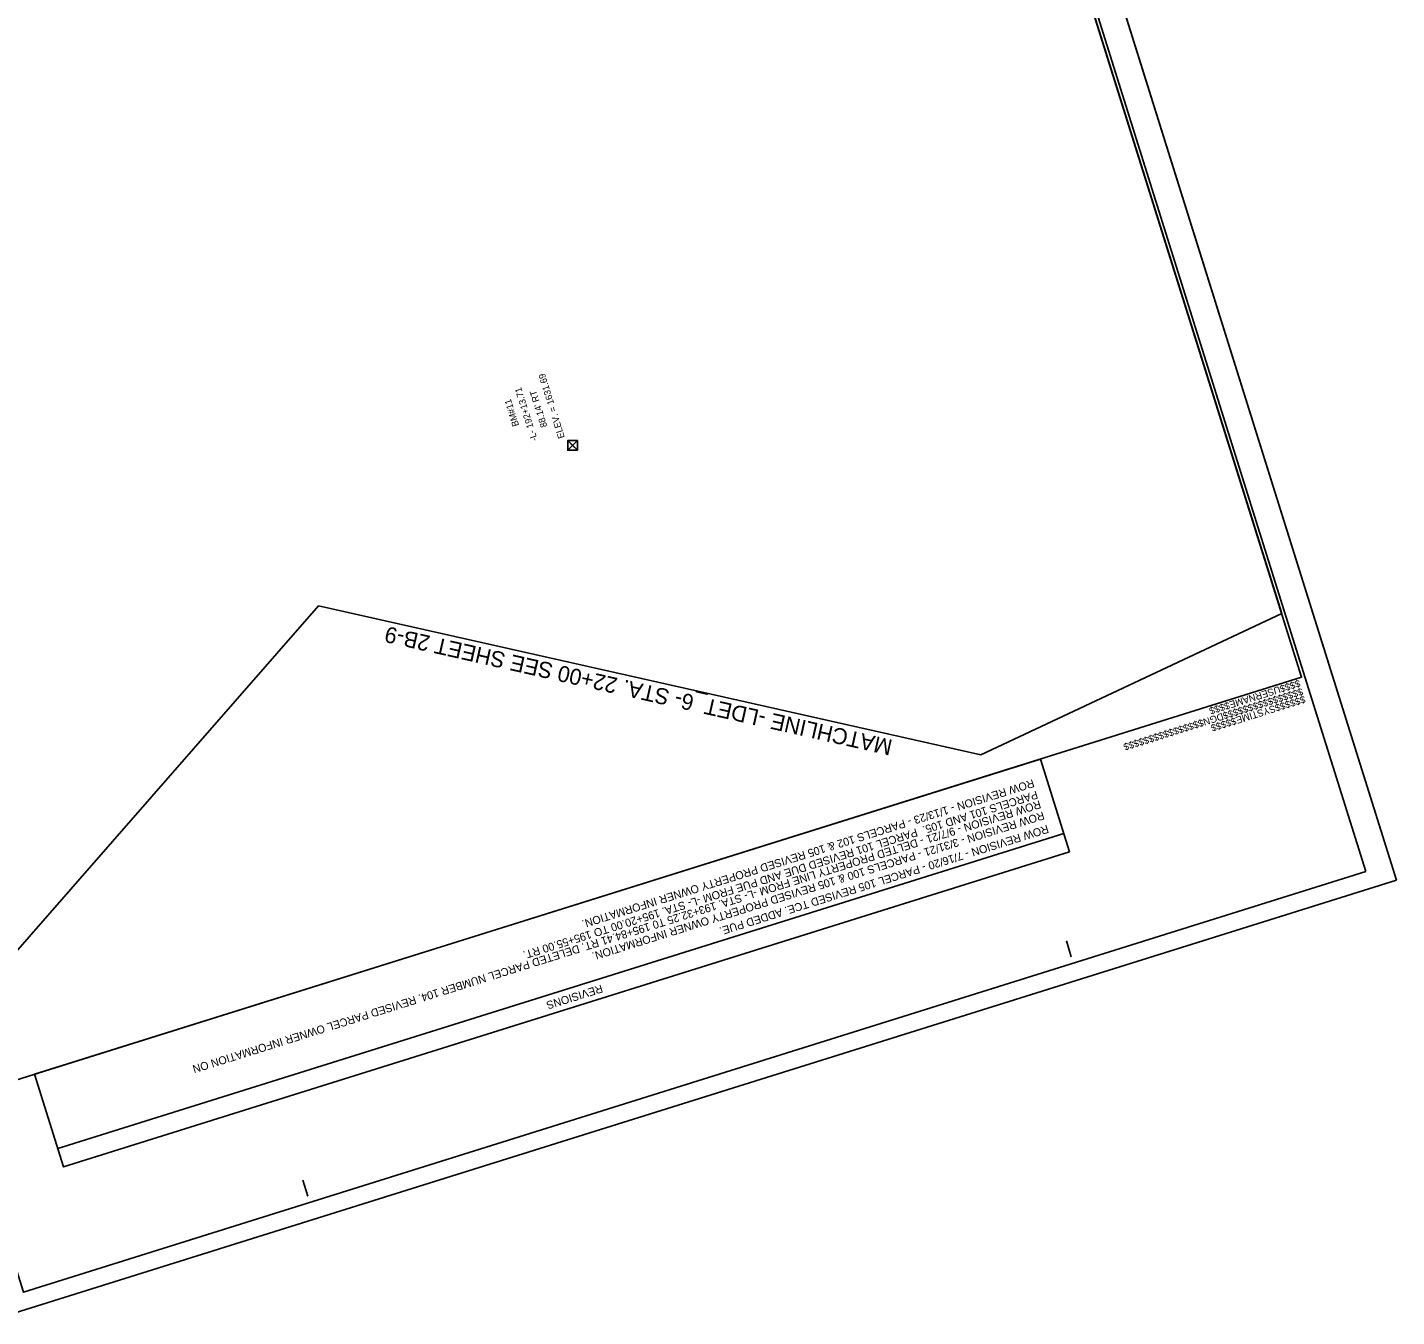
# Model space of a CAD drawing. Extents: x 473667 to 478950, y 494687 to 505998.
# Drawn here: x 474189 to 475215, y 504064 to 505031 of the extents above; entities that cross this region are included whole.
import ezdxf

# ---------------------------------------------------------------- set-up
doc = ezdxf.new("R2010")
doc.units = 0
for name, color, linetype in [('Default', 7, 'Continuous'), ('Matchline', 7, 'Continuous'), ('Matchline Text', 7, 'Continuous'), ('Sheet Block Revision CELL', 7, 'Continuous'), ('Sheet Cutting Line CELL', 7, 'Continuous'), ('Sheet Layout Plan Border', 7, 'Continuous'), ('Sheet Plan CELL', 7, 'Continuous'), ('Sheet Plan Layout CELL', 7, 'Continuous'), ('Sheet Plot Border Inside CELL', 7, 'Continuous'), ('Sheet Plot Border Outside CELL', 7, 'Continuous')]:
    doc.layers.add(name, color=color, linetype=linetype)

msp = doc.modelspace()

# ---------------------------------------------------------------- linework, layer by layer
at = {"layer": 'Default'}
msp.add_line((474597.4, 504717.3), (474597.4, 504717.3), dxfattribs=at)
msp.add_lwpolyline([(474593.8, 504720.9), (474601, 504720.9), (474601, 504713.7), (474593.8, 504713.7)], close=True, dxfattribs=at)
for points in [[(474601, 504720.9), (474593.8, 504713.7), (474597.4, 504717.3), (474601, 504713.7), (474593.8, 504720.9)], [(474597.4, 504717.3), (474601, 504720.9), (474593.8, 504720.9), (474597.4, 504717.3)], [(474597.4, 504717.3), (474593.8, 504713.7), (474601, 504713.7), (474597.4, 504717.3)]]:
    msp.add_lwpolyline(points, dxfattribs=at)
at = {"layer": 'Matchline'}
msp.add_line((474903.6, 504485.2), (474406.8, 504597), dxfattribs=at)
at = {"layer": 'Sheet Block Revision CELL'}
msp.add_line((474965.7, 504426.3), (474211.3, 504189.9), dxfattribs=at)
msp.add_lwpolyline([(474970.1, 504412.4), (474215.6, 504176.1), (474193.8, 504245.6), (474948.3, 504482)], close=True, dxfattribs=at)
at = {"layer": 'Sheet Cutting Line CELL'}
for p, q in [((475215.4, 504391.2), (474712.1, 505997.7)), ((474170.5, 504063.9), (475215.4, 504391.2))]:
    msp.add_line(p, q, dxfattribs=at)
at = {"layer": 'Sheet Layout Plan Border'}
msp.add_lwpolyline([(474406.8, 504597), (474903.6, 504485.2), (475129.2, 504591.1), (474710.6, 505927.1), (474746.7, 505812), (474670.3, 505788.1), (474619.3, 505950.9), (473859.3, 505712.8), (473919.1, 505521.9), (473753.5, 505470), (474127.2, 504277.2)], close=True, dxfattribs=at)
at = {"layer": 'Sheet Plan CELL'}
for p, q in [((475144.1, 504543.4), (475144.1, 504543.4)), ((474971.4, 504333.7), (474967.7, 504345.6)), ((474398.9, 504154.3), (474395.1, 504166.2))]:
    msp.add_line(p, q, dxfattribs=at)
for points in [[(473693.7, 505660.9), (474142.1, 504229.5), (475144.1, 504543.4), (474695.7, 505974.8)], [(475144.1, 504543.4), (474142.2, 504229.4), (473753.5, 505470), (473896.7, 505514.8), (473836.9, 505705.7), (474695.7, 505974.8)]]:
    msp.add_lwpolyline(points, close=True, dxfattribs=at)
at = {"layer": 'Sheet Plan Layout CELL'}
msp.add_lwpolyline([(474142.2, 504229.4), (475144.1, 504543.4), (474695.7, 505974.8), (473895.5, 505724.1), (473967.1, 505495.8), (473765.2, 505432.6)], close=True, dxfattribs=at)
at = {"layer": 'Sheet Plot Border Inside CELL'}
msp.add_lwpolyline([(475192.4, 504397.6), (474694.3, 505987.4), (473687.6, 505672.1), (474185.7, 504082.2)], close=True, dxfattribs=at)
at = {"layer": 'Sheet Plot Border Outside CELL'}
msp.add_lwpolyline([(475215.4, 504391.2), (474712.1, 505997.7), (473667.2, 505670.4), (474170.5, 504063.9)], close=True, dxfattribs=at)

# ---------------------------------------------------------------- texts
at = {"layer": 'Default'}
for s, p in [('ELEV. = 1631.69', (474591.6, 504723.3)), ('-L- 192+13.71', (474571.2, 504721.4)), ("88.14' RT", (474578.5, 504731.6)), ('BM#11', (474557.3, 504732.3))]:
    msp.add_text(s, height=5, rotation=107.3948, dxfattribs=at).set_placement(p)
at = {"layer": 'Matchline Text'}
msp.add_text('MATCHLINE -LDET_6- STA. 22+00 SEE SHEET 2B-9', height=12, rotation=167.3213, dxfattribs=at).set_placement((474838, 504496.3))
at = {"layer": 'Sheet Block Revision CELL'}
for s, p in [('PARCELS 101 AND 105.  PARCEL 101 REVISED DUE AND PUE FROM -L- STA. 195+20.00 TO 195+55.00 RT. ', (474945.2, 504458.4)), ('ROW REVISION - 1/13/23 - PARCELS 102 & 105 REVISED PROPERTY OWNER INFORMATION.', (474942.5, 504467)), ('ROW REVISION - 9/7/21 - DELTED PROPERTY LINE FROM -L- STA. 193+32.25 T0 195+84.41 RT. DELETED PARCEL NUMBER 104. REVISED PARCEL OWNER INFORMATION ON ', (474947.5, 504451.2)), ('ROW REVISION - 3/31/21 - PARCELS 100 & 105 REVISED PROPERTY OWNER INFORMATION.', (474950.1, 504442.8)), ('ROW REVISION - 7/16/20 - PARCEL 105 REVISED TCE. ADDED PUE.', (474953.3, 504432.7)), ('REVISIONS', (474618.9, 504313))]:
    msp.add_text(s, height=6, rotation=197.3948, dxfattribs=at).set_placement(p)
at = {"layer": 'Sheet Plan CELL'}
for s, p in [('$$$$USERNAME$$$$', (475142.2, 504541.6)), ('$$$$$$$$$$$$$$$$DGN$$$$$$$$$$$$$$$$', (475144.2, 504535.4)), ('$$$$$$SYSTIME$$$$$', (475146, 504529.6))]:
    msp.add_text(s, height=5.25, rotation=197.3948, dxfattribs=at).set_placement(p)

doc.saveas('drawing.dxf')
